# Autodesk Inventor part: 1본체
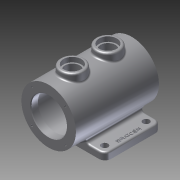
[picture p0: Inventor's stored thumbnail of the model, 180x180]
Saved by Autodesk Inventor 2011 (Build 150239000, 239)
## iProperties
Created: 2014-12
Part Number: 1본체
Document SubType Name: Modeling
Designer: user
Density: 1 g/cm^3
Author: user
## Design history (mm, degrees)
sketch "스케치1"
  geometry: L1 (0, 0)-(130, 0); L2 (130, 0)-(130, 95); L3 (130, 95)-(0, 95); L4 (0, 95)-(0, 0)
  constraints: 8 end point, 2 parallel, 1 horizontal, 1 perpendicular
  dimensions: "d0" = 130 distance of L3.end L2.end; "d1" = 95 distance of L2.end L1.end
extrude "돌출1" new body sketch "스케치1" distance "d2" = 12; taper "d3" = 0 deg
sketch "스케치2" dims "d23" = 37.5
  geometry: L1 (0, 0)-(0, 12) reference; L2 (0, 0)-(130, 0) reference; L3 (130, 12)-(130, 0) reference; L4 (130, 0)-(0, 0) reference; L5 (0, 0)-(0, 12) reference; L6 (0, 12)-(130, 12) reference; C1 r 46 at (65, 50)
  constraints: 1 centre point
  dimensions: "d4" = 92 diameter of C1; "d5" = 50 distance from line of L2 C1.centre; "d6" = 65 distance from line of L1 C1.centre
extrude "돌출2" join sketch "스케치2" distance "d7" = 30; taper "d9" = 0 deg; dims "d8" = 110, "d10" = 0
node "작업 평면1"
sketch "스케치3"
  geometry: L1 (-96, -30)-(-96, 110) reference; L2 (-96, 110)-(-4, 110) reference; L3 (-4, 110)-(-4, 95) reference; L4 (-4, 95)-(0, 95) reference; L5 (0, 95)-(0, 0) reference; L6 (0, 0)-(-4, 0) reference; L7 (-4, 0)-(-4, -30) reference; L8 (-4, -30)-(-96, -30) reference; L9 (-106, -10)-(-58.648, -10); L10 (-58.648, -10)-(-58.648, 10); L11 (-58.648, 10)-(-106, 10); L12 (-106, 10)-(-106, -10)
  constraints: 8 end point, 2 parallel, 1 horizontal, 1 perpendicular
  dimensions: "d11" = 40 distance between parallel lines of L8 L11; "d12" = 20 distance of L11.end L9.start; "d13" = 106 distance between parallel lines of L5 L12
revolve "회전1" sketch "스케치3" stored, may be unused: angle "d14" = 90 deg
sketch "스케치4"
  geometry: L1 (-4, 0)-(-4, -30) reference; L2 (-4, -30)-(-96, -30) reference; L3 (-96, -30)-(-96, -10) reference; L4 (-96, -10)-(-106, -10) reference; L5 (-106, -10)-(-106, 30) reference; L6 (-106, 30)-(-96, 30) reference; L7 (-96, 30)-(-96, 110) reference; L8 (-96, 110)-(-4, 110) reference; L9 (-4, 110)-(-4, 95) reference; L10 (-4, 95)-(0, 95) reference; L11 (0, 95)-(0, 0) reference; L12 (0, 0)-(-4, 0) reference; L13 (-106, 70)-(-64.183, 70); L14 (-64.183, 70)-(-64.183, 90); L15 (-64.183, 90)-(-106, 90); L16 (-106, 90)-(-106, 70)
  constraints: 8 end point, 2 parallel, 1 horizontal, 1 perpendicular
  dimensions: "d15" = 40 distance between parallel lines of L8 L13; "d16" = 20 distance of L15.end L13.start; "d17" = 106 distance between parallel lines of L11 L16
revolve "회전2" sketch "스케치4" stored, may be unused: angle "d18" = 90 deg
node "작업 평면2"
sketch "스케치5"
  geometry: L1 (-111, -30)-(-111, 110) reference; L2 (-111, 110)-(-19, 110) reference; L3 (-19, 110)-(-19, -30) reference; L4 (-19, -30)-(-111, -30) reference; L5 (-95, -42.03)-(-65, -42.03); L6 (-65, -42.03)-(-65, 144.703); L7 (-65, 144.703)-(-95, 144.703); L8 (-102.5, -18)-(-95, -18); L9 (-65, -18)-(-65, 98); L10 (-95, 98)-(-102.5, 98); L11 (-102.5, 98)-(-102.5, -18); L12 (-95, 144.703)-(-95, 98); L13 (-95, -18)-(-95, -42.03); 1 further point
  constraints: 18 end point, 5 parallel, 2 horizontal, 2 perpendicular, 1 point on line
  dimensions: "d20" = 46 distance between parallel lines of L1 L6; "d21" = 92 distance between parallel lines of L3 L1 (derived); "d23" = 37.5 distance between parallel lines of L6 L11; "d24" = 12 distance between parallel lines of L2 L10; "d25" = 12 distance between parallel lines of L4 L8
revolve "회전3" sketch "스케치5" stored, may be unused: angle "d26" = 90 deg
sketch "스케치6"
  geometry: C1 r 20 at (0, 0) reference; C2 r 20 at (0, -60) reference; 3 further points
  constraints: 2 coincident
hole "Hole1" sketch "스케치6" at (0, 0), (0, -60) diameter "d27" = 25; stored, may be unused: countersink angle "d31" = 90 deg, drill point angle "d33" = 118 deg; dims "d28" = 6, "d29" = 30, "d30" = 8, "d32" = 30
sketch "스케치7"
  geometry: L1 (0, 0)-(-53.702, 53.702); L2 (0, 0)-(75.945, 0); L3 (0, 0)-(0, 40); C1 r 46 at (0, 0) reference; C2 r 30 at (0, 0) reference; A1 r 40 centre (0, 0) between (-28.284, 28.284) and (0, 40); 1 further point
  constraints: 6 end point, 2 coincident, 2 point on circle, 1 centre point, 1 equal length, 1 horizontal, 1 point on line
  dimensions: "d34" = 135 deg angle of L2 L1; "d35" = 80 diameter of A1
hole "Hole2" sketch "스케치7" at (-28.284, 28.284) diameter "d36" = 3.242; stored, may be unused: countersink angle "d40" = 90 deg, drill point angle "d42" = 118 deg; dims "d37" = 8, "d38" = 30, "d39" = 8, "d41" = 10
node "작업 평면3"
fillet "모깎기1" dims "d46" = 10
sketch "스케치8"
  geometry: L1 (90.923, 110)-(90.923, 95) reference; L2 (90.923, 95)-(90.923, 0) reference; L3 (120, 0)-(90.923, 0) reference; L4 (130, 85)-(130, 10) reference; L5 (90.923, 95)-(120, 95) reference; L6 (39.077, 110)-(90.923, 110) reference; L7 (39.077, 95)-(39.077, 110) reference; L8 (10, 95)-(39.077, 95) reference; L9 (0, 10)-(0, 85) reference; L10 (39.077, 0)-(10, 0) reference; L11 (39.077, -30)-(39.077, 0) reference; L12 (90.923, -30)-(39.077, -30) reference; L13 (90.923, 0)-(90.923, -30) reference; L14 (39.077, 0)-(39.077, 95) reference; L15 (65, 120.179)-(65, -80.262); A1 r 10 centre (120, 10) between (120, 0) and (130, 10) reference; A2 r 10 centre (120, 85) between (130, 85) and (120, 95) reference; A3 r 10 centre (10, 85) between (10, 95) and (0, 85) reference; A4 r 10 centre (10, 10) between (0, 10) and (10, 0) reference; 5 further points
  constraints: 2 end point, 1 parallel
  dimensions: "d47" = 104 distance of point (13, 82.5) point (117, 82.5); "d48" = 25.92296 distance between parallel lines of L13 L15; "d49" = 65 distance between parallel lines of L15 L4 (derived); "d50" = 52 distance from line of L15 point (117, 82.5); "d51" = 12.5 distance from line of L5 point (117, 82.5); "d52" = 12.5 distance from line of L3 point (117, 12.5)
hole "Hole3" sketch "스케치8" at (13, 82.5), (117, 82.5), (117, 12.5), (13, 12.5) diameter "d53" = 11; stored, may be unused: countersink angle "d57" = 90 deg, drill point angle "d59" = 118 deg; dims "d54" = 8, "d55" = 30, "d56" = 8, "d58" = 30
fillet "모깎기2" dims "d60" = 3
fillet "모깎기3" dims "d61" = 3
fillet "모깎기4" dims "d62" = 5
fillet "모깎기5" dims "d63" = 3
sketch "스케치9"
  geometry: L1 (103.884, 0)-(120, 0) reference; L2 (120, 95)-(103.884, 95) reference; L3 (130, 10)-(130, 85) reference; C1 r 5.5 at (117, 12.5) reference; 2 further points
  constraints: 1 other
  dimensions: "d64" = 35 vertical distance of C1.centre point (122, 47.5); "d65" = 8 distance from line of L3 point (122, 47.5)
feature "엠보싱1" sketch "스케치9" dims "d0" = 130, "d1" = 95, "d66" = 1, "d67" = 0
chamfer "모따기1" distance "d68" = 1; stored, may be unused: second distance "d69" = 2, angle "d70" = 45 deg
node "솔리드1"
pattern_circular "원형 패턴1" dims angle "d44" = 360 deg
mirror "대칭1"
node "절단 모서리 투영1"
node "절단 모서리 투영2"
node "절단 모서리 투영3"
node "절단 모서리 투영4"
node "절단 모서리 투영5"
node "절단 모서리 투영6"
